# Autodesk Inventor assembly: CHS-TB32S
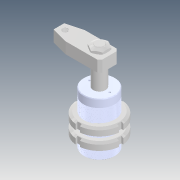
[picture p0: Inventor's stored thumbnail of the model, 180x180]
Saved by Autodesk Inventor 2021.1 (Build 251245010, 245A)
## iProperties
Created: 2020-02
Part Number: CHS-TB32S
Description: STEP AP214
Document SubType Name: Assembly
Designer: user
Title: chs-tb32s_asm.STEP
Revision Number: ÈÎºÎ
Sending System: SolidWorks 2016
Preprocessor: SwSTEP 2.0
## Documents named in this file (6)
- D:\Vault_2016\Projekty\Clamptek\Hydraulic\CHS\CHS-32\Inventor\CHS-TB32S\CHS-TB32S.iam
- D:\Vault_2016\Projekty\Clamptek\Hydraulic\CHS\CHS-32\Inventor\CHS-TB32S\CHS-TB32-03_1.ipt
- D:\Vault_2016\Projekty\Clamptek\Hydraulic\CHS\CHS-32\Inventor\CHS-TB32S\CHS-32S-02_6.ipt
- D:\Vault_2016\Projekty\Clamptek\Hydraulic\CHS\CHS-32\Inventor\CHS-TB32S\CHS-32S-01_8.ipt
- D:\Vault_2016\Projekty\Clamptek\Hydraulic\CHS\CHS-32\Inventor\CHS-TB32S\M16_8.ipt
- D:\Vault_2016\Projekty\Clamptek\Hydraulic\CHS\CHS-32\Inventor\CHS-TB32S\CHS-TB32-04_1.ipt
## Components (6 placed, 6 different names)
1. CHS-TB32-03_1_1
2. CHS-32S-02_6_2
3. CHS-32S-01_8_3
4. M16_8_4
5. CHS-TB32-04_1_5
6. CHS-TB32-04_1_6
